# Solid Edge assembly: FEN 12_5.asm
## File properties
Title: Zylinder
Author: bmolnar
Template: iso assembly.asm
Last saved by: bmolnar
Revision: 7
Application: Solid Edge
Username: bmolnar
Dokumentum tartalom típus: 1
Document Number: FEN 12/5
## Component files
Kolbenstange.par
Profilrohr.par
Kit.par
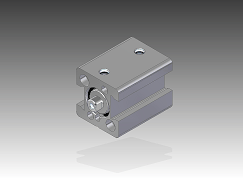
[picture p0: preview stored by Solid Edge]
